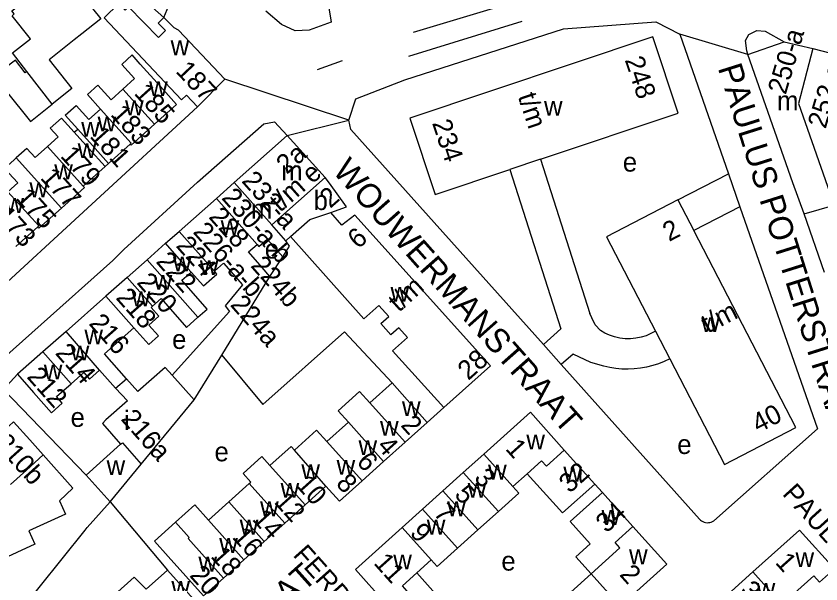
# Model space of a CAD drawing. Extents: x 161775 to 163181, y 382878 to 383925.
# Drawn here: x 162768.1 to 162935.1, y 383562.8 to 383680.7 of the extents above; entities that cross this region are included whole.
import ezdxf

# ---------------------------------------------------------------- set-up
doc = ezdxf.new("R2010")
doc.units = 0
for name, color, linetype in [('BLT_Basislijn', 7, 'Continuous'), ('BLT_Bebouwing', 7, 'Continuous'), ('BLT_Centroide', 7, 'Continuous'), ('BLT_Huisnummer', 7, 'Continuous'), ('BLT_Huisnummer_ tussenligend', 7, 'Continuous'), ('BLT_Huisnummer_reeks', 7, 'Continuous'), ('BLT_Onderdoorgang_en_onderverdeling', 7, 'Continuous'), ('BLT_Onderverdeling_panden', 7, 'Continuous'), ('BLT_Straatnaam', 7, 'Continuous'), ('BLT_Straatnaam_verkleind', 7, 'Continuous'), ('BLT_Vlakafsluiter', 7, 'Continuous')]:
    doc.layers.add(name, color=color, linetype=linetype)

msp = doc.modelspace()

# ---------------------------------------------------------------- linework, layer by layer
at = {"layer": 'BLT_Basislijn'}
for p, q in [((162798.8, 383680.44), (162788.81, 383689.19)), ((162850.56, 383677.36), (162869.25, 383682.97)), ((162849.63, 383672.38), (162873.16, 383679.63)), ((162881.71, 383678.05), (162900.86, 383679.52)), ((162900.86, 383679.52), (162905.85, 383676.94)), ((162848.81, 383667.44), (162881.71, 383678.05)), ((162905.85, 383676.94), (162915.94, 383647.99)), ((162830.68, 383669.64), (162835.84, 383671.51)), ((162838.6, 383663.54), (162848.81, 383667.44)), ((162837.13, 383659.08), (162838.6, 383663.54)), ((162837.59, 383657.15), (162837.13, 383659.08)), ((162877.54, 383612.5), (162837.59, 383657.15)), ((162876.96, 383650.99), (162887.21, 383618.94)), ((162870.56, 383648.84), (162881.13, 383615.79)), ((162905.47, 383642.58), (162915.94, 383647.99)), ((162915.94, 383647.99), (162918.33, 383641.13)), ((162918.33, 383641.13), (162908.78, 383636.19)), ((162918.33, 383641.13), (162934.41, 383595.01)), ((162820.79, 383626.63), (162823.48, 383630.71)), ((162887.56, 383618.06), (162887.21, 383618.94)), ((162888.28, 383616.64), (162887.56, 383618.06)), ((162881.13, 383615.79), (162877.54, 383612.5)), ((162889.36, 383615.42), (162888.28, 383616.64)), ((162881.21, 383608.4), (162877.54, 383612.5)), ((162883.7, 383610.52), (162881.21, 383608.4)), ((162887.36, 383608.78), (162883.7, 383610.52)), ((162890.07, 383608.02), (162887.36, 383608.78)), ((162881.21, 383608.4), (162909.95, 383576.27)), ((162768.38, 383606.35), (162765.52, 383603.22)), ((162765.52, 383603.22), (162782.64, 383585.42)), ((162853.39, 383596.32), (162856.9, 383599.42)), ((162934.41, 383595.01), (162912.89, 383575.92)), ((162888.2, 383583.57), (162889.8, 383581.79)), ((162787.66, 383579.84), (162782.89, 383574.55)), ((162787.66, 383579.84), (162799.52, 383565.69))]:
    msp.add_line(p, q, dxfattribs=at)
for points in [[(162853.7, 383711.28), (162856.29, 383708.62), (162856.52, 383707.48), (162851.68, 383702.53), (162833.55, 383686.54), (162832.46, 383685.79), (162833.5, 383679.47), (162828.96, 383677.8), (162826.05, 383677.67), (162823.21, 383678.95), (162819.92, 383681.73)], [(162919.98, 383672.72), (162919.74, 383673.48), (162919.51, 383675.63), (162920.15, 383676.88), (162921.83, 383677.7), (162923.56, 383677.57), (162927.51, 383675.33)], [(162805.75, 383661.89), (162761.83, 383621.46), (162732.09, 383594.83), (162724.39, 383587.57), (162723.59, 383586.62), (162709.65, 383574.02)], [(162725.94, 383574.02), (162727.2, 383575.2), (162740.08, 383586.57), (162758.35, 383603.41), (162788.21, 383630), (162790.45, 383632.28), (162805.73, 383646.24), (162819.54, 383658.33), (162821.71, 383658.73), (162824.34, 383655.92)], [(162810.79, 383610.33), (162819.34, 383600.05), (162836.23, 383615.17), (162846.14, 383604.54)], [(162900.8, 383615.28), (162899.87, 383614.78), (162898.88, 383614.35), (162897.83, 383614.03), (162896.74, 383613.81), (162895.62, 383613.71), (162894.5, 383613.72), (162893.38, 383613.85), (162892.29, 383614.1), (162891.25, 383614.45), (162890.27, 383614.89), (162889.36, 383615.42)], [(162903.75, 383609.57), (162902.62, 383609.02), (162901.44, 383608.55), (162900.22, 383608.16), (162898.97, 383607.84), (162897.7, 383607.61), (162896.41, 383607.47), (162895.12, 383607.41), (162893.83, 383607.44), (162892.56, 383607.55), (162891.3, 383607.74), (162890.07, 383608.02)], [(162773.75, 383589.62), (162779.87, 383582.72), (162777.1, 383580.07), (162778.37, 383577.32), (162770.77, 383573.84)], [(162909.95, 383576.27), (162910.15, 383576.08), (162910.38, 383575.91), (162910.63, 383575.77), (162910.91, 383575.66), (162911.2, 383575.58), (162911.51, 383575.54), (162911.81, 383575.55), (162912.11, 383575.59), (162912.39, 383575.67), (162912.65, 383575.78), (162912.89, 383575.92)], [(162728.69, 383516.08), (162748.72, 383535.7), (162761.22, 383547.63), (162761.76, 383548.52), (162763.29, 383550.17), (162782.46, 383574.02)], [(162770.77, 383573.84), (162772.03, 383571.07), (162764.47, 383567.61), (162765.74, 383564.84), (162758.22, 383561.4)], [(162782.46, 383574.02), (162782.89, 383574.55)]]:
    msp.add_lwpolyline(points, dxfattribs=at)
at = {"layer": 'BLT_Bebouwing'}
for p, q in [((162919.98, 383672.72), (162927.51, 383675.33)), ((162927.51, 383675.33), (162933.48, 383674.01)), ((162933.48, 383674.01), (162949.2, 383669.76)), ((162929.33, 383646.12), (162919.98, 383672.72)), ((162780.18, 383656.58), (162780.92, 383657.22)), ((162824.34, 383655.92), (162813.4, 383646.18)), ((162832.26, 383647.17), (162824.34, 383655.92)), ((162791.75, 383654.13), (162787.3, 383650.13)), ((162876.96, 383650.99), (162870.56, 383648.84)), ((162786.57, 383649.47), (162782.06, 383645.4)), ((162786.57, 383649.47), (162787.3, 383650.13)), ((162813.4, 383646.18), (162809.67, 383642.86)), ((162931.64, 383639.62), (162929.33, 383646.12)), ((162809.67, 383642.86), (162801.96, 383636)), ((162905.47, 383642.58), (162908.78, 383636.19)), ((162935.88, 383627.49), (162931.64, 383639.62)), ((162772.59, 383636.94), (162768.09, 383632.89)), ((162799.15, 383633.54), (162801.96, 383636)), ((162799.15, 383633.54), (162795.29, 383630.12)), ((162825.03, 383634.92), (162824.09, 383634.08)), ((162795.29, 383630.12), (162791.15, 383626.45)), ((162791.15, 383626.45), (162786.75, 383622.56)), ((162810.79, 383610.33), (162820.79, 383626.63)), ((162786.75, 383622.56), (162778.48, 383615.26)), ((162778.48, 383615.26), (162773.69, 383610.99)), ((162900.8, 383615.28), (162903.75, 383609.57)), ((162773.69, 383610.99), (162768.38, 383606.35)), ((162785.43, 383607.19), (162788.74, 383603.44)), ((162856.9, 383599.42), (162866.58, 383608.1)), ((162793.39, 383602.76), (162791.03, 383605.43)), ((162841.54, 383600.41), (162846.14, 383604.54)), ((162846.14, 383604.54), (162853.39, 383596.32)), ((162794.09, 383587.66), (162805.09, 383601.05)), ((162874.84, 383598.45), (162865.17, 383589.77)), ((162881.88, 383590.61), (162874.84, 383598.45)), ((162832.61, 383592.4), (162837.07, 383596.41)), ((162853.39, 383596.32), (162848.86, 383592.26)), ((162789.81, 383591.81), (162782.64, 383585.42)), ((162848.86, 383592.26), (162844.39, 383588.25)), ((162820.8, 383587.4), (162825.2, 383591.35)), ((162825.2, 383591.35), (162825.86, 383590.62)), ((162888.2, 383583.57), (162881.88, 383590.61)), ((162770.24, 383586.45), (162773.75, 383589.62)), ((162865.17, 383589.77), (162860.92, 383585.96)), ((162787.66, 383579.84), (162794.09, 383587.66)), ((162844.39, 383588.25), (162839.93, 383584.24)), ((162766.97, 383583.49), (162770.24, 383586.45)), ((162782.64, 383585.42), (162787.66, 383579.84)), ((162860.92, 383585.96), (162856.68, 383582.15)), ((162871.2, 383583.04), (162874.18, 383585.71)), ((162874.18, 383585.71), (162881.5, 383577.56)), ((162812.27, 383579.84), (162816.51, 383583.65)), ((162839.93, 383584.24), (162835.23, 383580.03)), ((162881.5, 383577.56), (162888.2, 383583.57)), ((162828.11, 383579.26), (162832.42, 383583.13)), ((162835.23, 383580.03), (162832.42, 383583.13)), ((162856.68, 383582.15), (162852.44, 383578.35)), ((162808.03, 383576.04), (162812.27, 383579.84)), ((162823.87, 383575.46), (162828.11, 383579.26)), ((162852.44, 383578.35), (162848.2, 383574.54)), ((162863.95, 383574.05), (162868.2, 383577.86)), ((162819.62, 383571.65), (162823.87, 383575.46)), ((162848.2, 383574.54), (162838.53, 383565.85)), ((162859.71, 383570.24), (162863.95, 383574.05)), ((162921.02, 383565.33), (162930.69, 383574.01)), ((162930.69, 383574.01), (162937.93, 383565.94)), ((162815.38, 383567.85), (162819.62, 383571.65)), ((162807.02, 383560.35), (162799.67, 383568.53)), ((162811.14, 383564.04), (162815.38, 383567.85)), ((162851.26, 383565.14), (162854.24, 383567.81)), ((162795.13, 383561.74), (162799.52, 383565.69)), ((162799.52, 383565.69), (162805.56, 383558.97)), ((162838.53, 383565.85), (162845.57, 383558.01)), ((162858.59, 383556.98), (162851.26, 383565.14)), ((162916.55, 383561.32), (162921.02, 383565.33)), ((162811.14, 383564.04), (162807.02, 383560.35))]:
    msp.add_line(p, q, dxfattribs=at)
for points in [[(162788.81, 383689.19), (162782.49, 383684.15), (162785.68, 383680.16), (162781.77, 383677.04), (162780.16, 383675.75)], [(162770.37, 383669.19), (162767.38, 383673.06), (162771.11, 383675.95), (162767.27, 383680.77), (162767.74, 383681.15), (162767.24, 383681.78), (162770.39, 383684.29), (162770.89, 383683.67), (162772.7, 383685.11)], [(162798.8, 383680.44), (162797.58, 383679.25), (162799.12, 383677.68), (162797.69, 383676.28), (162791.47, 383682.65), (162790.75, 383681.95), (162789.43, 383683.31), (162786.37, 383680.32), (162802.45, 383663.3), (162803.49, 383664.28), (162805.75, 383661.89)], [(162811.44, 383667.59), (162801.8, 383677.79), (162800.9, 383678.29), (162798.8, 383680.44)], [(162780.16, 383675.75), (162774.95, 383671.6), (162779.66, 383665.7), (162775.59, 383662.44)], [(162876.96, 383650.99), (162905.54, 383660.57), (162900.23, 383676.41), (162849.79, 383659.49), (162855.1, 383643.66), (162870.56, 383648.84)], [(162770.37, 383669.19), (162770.01, 383668.91), (162767.96, 383671.55), (162765.73, 383669.82), (162763.92, 383672.14), (162763.08, 383672.84), (162761.8, 383673.28), (162761.69, 383672.54), (162760.81, 383671.87)], [(162796.85, 383658.27), (162801.42, 383662.38), (162798.07, 383666.1), (162793.89, 383670.74), (162792.19, 383672.63), (162790.02, 383670.68), (162792.71, 383667.73), (162790.27, 383665.53)], [(162805.75, 383661.89), (162811.44, 383667.59)], [(162790.27, 383665.53), (162787.83, 383663.33), (162785.08, 383666.38), (162782.9, 383664.42), (162785.61, 383661.41)], [(162760.55, 383660.74), (162763.25, 383662.9), (162766.07, 383665.15), (162771.1, 383658.85), (162775.59, 383662.44)], [(162780.92, 383657.22), (162778.3, 383660.12), (162780.56, 383662.15), (162783.19, 383659.23), (162785.61, 383661.41)], [(162780.18, 383656.58), (162777.51, 383659.53), (162775.21, 383657.46), (162776.85, 383655.64), (162774.63, 383653.65)], [(162796.85, 383658.27), (162791.98, 383653.88), (162791.75, 383654.13)], [(162774.63, 383653.65), (162772.06, 383651.33), (162770.33, 383653.24), (162768.13, 383651.26)], [(162768.13, 383651.26), (162767.7, 383650.86), (162765.72, 383649.09), (162768.45, 383646.06), (162766.43, 383644.24)], [(162833.41, 383639.92), (162836.68, 383641.08), (162833.18, 383646.03), (162832.26, 383647.17)], [(162782.06, 383645.4), (162782.28, 383645.15), (162777.5, 383640.85)], [(162905.47, 383642.58), (162890.64, 383634.9), (162900.8, 383615.28)], [(162777.5, 383640.85), (162772.85, 383636.66), (162772.59, 383636.94)], [(162866.58, 383608.1), (162838.42, 383639.4), (162835.74, 383637.31), (162833.41, 383639.92)], [(162903.75, 383609.57), (162915.09, 383587.65), (162929.92, 383595.33), (162908.78, 383636.19)], [(162818.11, 383633.3), (162818.51, 383632.85), (162820.24, 383634.37), (162823.48, 383630.71)], [(162823.48, 383630.71), (162824.85, 383632.95), (162824.09, 383634.08)], [(162856.9, 383599.42), (162846.23, 383611.22), (162849.31, 383613.98), (162847.51, 383616), (162845.89, 383614.55), (162843.83, 383616.86), (162845.45, 383618.31), (162843.38, 383620.62), (162840.29, 383617.86), (162825.03, 383634.92)], [(162820.79, 383626.63), (162819.21, 383628.49), (162816.34, 383631.74), (162818.11, 383633.3)], [(162809.27, 383627.72), (162811.16, 383629.38), (162815.13, 383624.89), (162811.52, 383620.57), (162812.42, 383619.38), (162800.51, 383606.16)], [(162805.85, 383618.17), (162807.79, 383619.88), (162802.51, 383625.86), (162804.43, 383627.56)], [(162804.43, 383627.56), (162806.98, 383624.68), (162808.73, 383626.22)], [(162808.73, 383626.22), (162809.78, 383627.14), (162809.27, 383627.72)], [(162796.44, 383620.46), (162798.24, 383622.05), (162803.49, 383616.09), (162805.85, 383618.17)], [(162792.56, 383615.99), (162795.63, 383612.51), (162797.66, 383614.31), (162795.67, 383616.57), (162797.71, 383618.38), (162796.12, 383620.18), (162796.44, 383620.46)], [(162791.03, 383605.43), (162786.46, 383610.6), (162792.56, 383615.99)], [(162805.09, 383601.05), (162810.79, 383610.33)], [(162779.52, 383604.39), (162782.16, 383606.72), (162783.36, 383605.36), (162785.43, 383607.19)], [(162800.51, 383606.16), (162799.06, 383607.77), (162793.39, 383602.76)], [(162768.38, 383606.35), (162771.7, 383602.6), (162775.44, 383598.36), (162777.69, 383600.35), (162776.49, 383601.71), (162779.52, 383604.39)], [(162788.74, 383603.44), (162791.22, 383600.83), (162786.71, 383596.9), (162786.02, 383596.1), (162789.81, 383591.81)], [(162837.07, 383596.41), (162834.94, 383598.79), (162839.4, 383602.8), (162841.54, 383600.41)], [(162773.75, 383589.62), (162770.93, 383592.75), (162767.57, 383596.46), (162765.76, 383594.82), (162761.72, 383599.29)], [(162825.86, 383590.62), (162830.48, 383594.77), (162832.61, 383592.4)], [(162816.51, 383583.65), (162816.85, 383583.96), (162815.22, 383585.78), (162819.12, 383589.28), (162820.8, 383587.4)], [(162868.2, 383577.86), (162872.44, 383581.67), (162871.2, 383583.04)], [(162887.45, 383564.95), (162884.3, 383568.45), (162887.28, 383571.13), (162883.11, 383575.77), (162889.8, 383581.79)], [(162889.8, 383581.79), (162896.12, 383574.75)], [(162801.18, 383575.64), (162805.17, 383579.22), (162808.03, 383576.04)], [(162799.67, 383568.53), (162796.8, 383571.71), (162801.18, 383575.64)], [(162896.12, 383574.75), (162903.16, 383566.9), (162893.49, 383558.22)], [(162854.24, 383567.81), (162855.47, 383566.44), (162859.71, 383570.24)], [(162790.88, 383557.94), (162788.52, 383560.57), (162792.61, 383564.24), (162795.13, 383561.74)], [(162883.21, 383561.14), (162887.45, 383564.95)]]:
    msp.add_lwpolyline(points, dxfattribs=at)
at = {"layer": 'BLT_Onderdoorgang_en_onderverdeling'}
for points in [[(162787.3, 383650.13), (162783.96, 383653.84), (162780.92, 383657.22)], [(162786.57, 383649.47), (162783.23, 383653.19), (162780.18, 383656.58)], [(162804.43, 383627.56), (162802.46, 383629.79), (162799.15, 383633.54)]]:
    msp.add_lwpolyline(points, dxfattribs=at)
at = {"layer": 'BLT_Onderverdeling_panden'}
for p, q in [((162775.59, 383662.44), (162770.37, 383669.19)), ((162790.27, 383665.53), (162796.85, 383658.27)), ((162774.63, 383653.65), (162782.06, 383645.4)), ((162768.13, 383651.26), (162777.5, 383640.85)), ((162832.26, 383647.17), (162821.18, 383637.38)), ((162821.18, 383637.38), (162813.4, 383646.18)), ((162818.11, 383633.3), (162809.67, 383642.86)), ((162931.64, 383639.62), (162937.86, 383641.48)), ((162824.09, 383634.08), (162821.18, 383637.38)), ((162801.96, 383636), (162809.27, 383627.72)), ((162805.85, 383618.17), (162795.29, 383630.12)), ((162796.44, 383620.46), (162791.15, 383626.45)), ((162792.56, 383615.99), (162786.75, 383622.56)), ((162785.43, 383607.19), (162778.48, 383615.26)), ((162779.52, 383604.39), (162773.69, 383610.99)), ((162788.74, 383603.44), (162791.03, 383605.43)), ((162800.51, 383606.16), (162805.09, 383601.05)), ((162848.86, 383592.26), (162841.54, 383600.41)), ((162837.07, 383596.41), (162844.39, 383588.25)), ((162839.93, 383584.24), (162832.61, 383592.4)), ((162832.42, 383583.13), (162825.86, 383590.62)), ((162865.17, 383589.77), (162871.2, 383583.04)), ((162828.11, 383579.26), (162820.8, 383587.4)), ((162860.92, 383585.96), (162868.2, 383577.86)), ((162823.87, 383575.46), (162816.51, 383583.65)), ((162856.68, 383582.15), (162863.95, 383574.05)), ((162819.62, 383571.65), (162812.27, 383579.84)), ((162852.44, 383578.35), (162859.71, 383570.24)), ((162815.38, 383567.85), (162808.03, 383576.04)), ((162848.2, 383574.54), (162854.24, 383567.81)), ((162927.06, 383558.6), (162921.02, 383565.33)), ((162893.49, 383558.22), (162887.45, 383564.95))]:
    msp.add_line(p, q, dxfattribs=at)
for points in [[(162933.48, 383674.01), (162930.46, 383662.53), (162937.86, 383641.48)], [(162785.61, 383661.41), (162791.97, 383654.33), (162791.75, 383654.13)], [(162766.43, 383644.24), (162772.82, 383637.14), (162772.59, 383636.94)], [(162825.03, 383634.92), (162829.05, 383638.45), (162833.41, 383639.92)], [(162789.81, 383591.81), (162790.17, 383592.12), (162794.09, 383587.66)], [(162881.88, 383590.61), (162878.16, 383587.27), (162877.16, 383588.39), (162874.18, 383585.71)], [(162801.18, 383575.64), (162804.04, 383572.45), (162803.79, 383572.23), (162811.14, 383564.04)], [(162887.45, 383564.95), (162893.4, 383570.29), (162892.4, 383571.41), (162896.12, 383574.75)], [(162845.57, 383558.01), (162849.29, 383561.35), (162848.29, 383562.46), (162851.26, 383565.14)], [(162927.06, 383558.6), (162933.64, 383564.51), (162934.84, 383563.17), (162937.93, 383565.94)]]:
    msp.add_lwpolyline(points, dxfattribs=at)
at = {"layer": 'BLT_Vlakafsluiter'}
for p, q in [((162798.8, 383680.44), (162805.12, 383695.66)), ((162919.98, 383672.72), (162905.85, 383676.94)), ((162837.13, 383659.08), (162811.44, 383667.59)), ((162824.34, 383655.92), (162837.13, 383659.08))]:
    msp.add_line(p, q, dxfattribs=at)

# ---------------------------------------------------------------- texts
at = {"layer": 'BLT_Centroide'}
for s, p in [('w', (162800.18, 383672.59)), ('w', (162795.72, 383664.09)), ('m', (162926.02, 383661.14)), ('w', (162790.73, 383660.12)), ('w', (162877.66, 383660.03)), ('w', (162781.62, 383655.64)), ('w', (162785.03, 383656.77)), ('w', (162780.89, 383651.23)), ('e', (162894.02, 383648.42)), ('w', (162776.03, 383646.84)), ('m', (162823.12, 383646.62)), ('w', (162770.88, 383643.09)), ('b', (162829.84, 383640.44)), ('w', (162765.88, 383639.84)), ('m', (162816.84, 383638.67)), ('w', (162810.56, 383635.25)), ('e', (162819.71, 383630.38)), ('w', (162800.66, 383627.72)), ('w', (162806.24, 383626.96)), ('w', (162796.66, 383623.88)), ('w', (162792.12, 383620.47)), ('w', (162845.81, 383621.42)), ('w', (162910.28, 383615.11)), ('w', (162782.28, 383612.57)), ('e', (162800.48, 383611.61)), ('w', (162779.45, 383609.23)), ('w', (162773.86, 383605.28)), ('w', (162848.19, 383597.66)), ('e', (162779.41, 383595.43)), ('i', (162790.5, 383594.81)), ('w', (162843.64, 383593.58)), ('w', (162874, 383590.75)), ('w', (162839.17, 383589.58)), ('e', (162905.32, 383589.8)), ('e', (162809.28, 383588.28)), ('w', (162786.89, 383585.42)), ('w', (162834.62, 383585.5)), ('w', (162827.31, 383584.58)), ('w', (162866.06, 383584.5)), ('w', (162881.69, 383584.09)), ('w', (162823, 383580.7)), ('w', (162861.83, 383580.7)), ('w', (162818.75, 383576.89)), ('w', (162857.58, 383576.89)), ('w', (162889.61, 383575.08)), ('w', (162814.52, 383573.08)), ('w', (162853.34, 383573.08)), ('w', (162810.27, 383569.27)), ('w', (162805.95, 383565.39)), ('w', (162846.38, 383565.83)), ('e', (162868.81, 383565.59)), ('w', (162895.31, 383566.92)), ('w', (162929.86, 383566.31)), ('w', (162800.34, 383560.36)), ('w', (162921.8, 383559.95))]:
    msp.add_text(s, height=4, dxfattribs=at).set_placement(p)
at = {"layer": 'BLT_Huisnummer'}
for s, rotation, p in [('187', 313.3788, (162801.07, 383669.13)), ('185', 312.0105, (162792.43, 383664.59)), ('181', 312.0026, (162783.24, 383655.66)), ('179', 312.0026, (162777.13, 383651.58)), ('175', 312.0015, (162767.87, 383642.84)), ('230-a-b', 311.4651, (162810.59, 383642.88)), ('2', 41.458, (162833.3, 383640.67)), ('224', 311.4651, (162801.13, 383632.94)), ('220', 311.4651, (162793, 383625.3)), ('216', 311.4688, (162783.06, 383616.79)), ('212', 311.4651, (162770.17, 383605.75)), ('216a', 311.4688, (162789.71, 383596.96)), ('2', 311.8923, (162847.77, 383595.69)), ('1', 311.9151, (162869.5, 383590.8)), ('6', 311.891, (162838.58, 383588.05)), ('32', 41.9195, (162882.99, 383581.5)), ('10', 311.9037, (162825.98, 383583.28)), ('5', 311.9151, (162858.89, 383581.25)), ('34', 41.9199, (162890.63, 383573.25)), ('14', 311.8912, (162816.93, 383576.2)), ('18', 311.9036, (162808.32, 383568.45)), ('11', 311.9151, (162842.15, 383567.08)), ('1', 311.9198, (162925.49, 383567.19)), ('2', 311.9151, (162893.18, 383564.69)), ('3', 311.9198, (162918.13, 383561.32))]:
    msp.add_text(s, height=4, rotation=rotation, dxfattribs=at).set_placement(p)
at = {"layer": 'BLT_Huisnummer_ tussenligend'}
for s, rotation, p in [('183', 312.0105, (162787.55, 383660.18)), ('177', 312.0015, (162772.97, 383647.03)), ('173', 311.9929, (162763.64, 383639.04)), ('222', 311.4651, (162796.97, 383629.66)), ('218', 311.4688, (162788.65, 383622.14)), ('214', 311.4651, (162776.07, 383610.65)), ('4', 311.8923, (162842.81, 383591.3)), ('3', 311.9151, (162862.97, 383584.68)), ('8', 311.891, (162834.31, 383583.55)), ('12', 311.9037, (162821.47, 383579.76)), ('7', 311.9151, (162854.59, 383577.39)), ('9', 311.9151, (162849.66, 383573.3)), ('16', 311.8912, (162812.78, 383572.47)), ('20', 311.9036, (162803.93, 383564.51))]:
    msp.add_text(s, height=4, rotation=rotation, dxfattribs=at).set_placement(p)
at = {"layer": 'BLT_Huisnummer_reeks'}
for s, rotation, p in [('250-a', 73.4976, (162927.82, 383664.24)), ('252-a-b', 73.4994, (162936.1, 383657.16)), ('248', 288.5369, (162894.39, 383671.63)), ('t/m', 288.5369, (162872.2, 383664.06)), ('234', 288.5369, (162854.4, 383658.53)), ('2a', 41.458, (162824.28, 383647.72)), ('t/m e', 41.458, (162822.9, 383639.84)), ('232-a', 311.4561, (162814.76, 383646.39)), ('228', 311.4611, (162807.92, 383638.92)), ('226-a-b', 311.4611, (162804.66, 383635.81)), ('6', 41.3362, (162839.09, 383632.22)), ('2', 27.3614, (162903.61, 383633.81)), ('224b', 311.4611, (162816.63, 383628.79)), ('t/m', 41.9179, (162847.54, 383619.09)), ('224a', 311.4611, (162812.39, 383620.69)), ('t/m', 27.3614, (162911.63, 383614.76)), ('28', 41.9179, (162861.96, 383604.94)), ('40', 27.3614, (162922.12, 383594.08)), ('210b', 312.0994, (162763.43, 383591.88))]:
    msp.add_text(s, height=4, rotation=rotation, dxfattribs=at).set_placement(p)
at = {"layer": 'BLT_Straatnaam'}
for s, height, rotation, p in [('PAULUS POTTERSTRAAT', 5, 287.5274, (162913.71, 383669.95)), ('WOUWERMANSTRAAT', 5, 311.5973, (162833.61, 383648.4)), ('FERDINAND BOLSTRAAT', 4, 311.7055, (162825.42, 383568.75)), ('FRANS HALSSTRAAT', 5, 41.8155, (162779.84, 383518.22))]:
    msp.add_text(s, height=height, rotation=rotation, dxfattribs=at).set_placement(p)
at = {"layer": 'BLT_Straatnaam_verkleind'}
msp.add_text('PAULUS POTTERSTRAAT', height=4, rotation=312.2351, dxfattribs=at).set_placement((162926.97, 383581.42))

doc.saveas('drawing.dxf')
